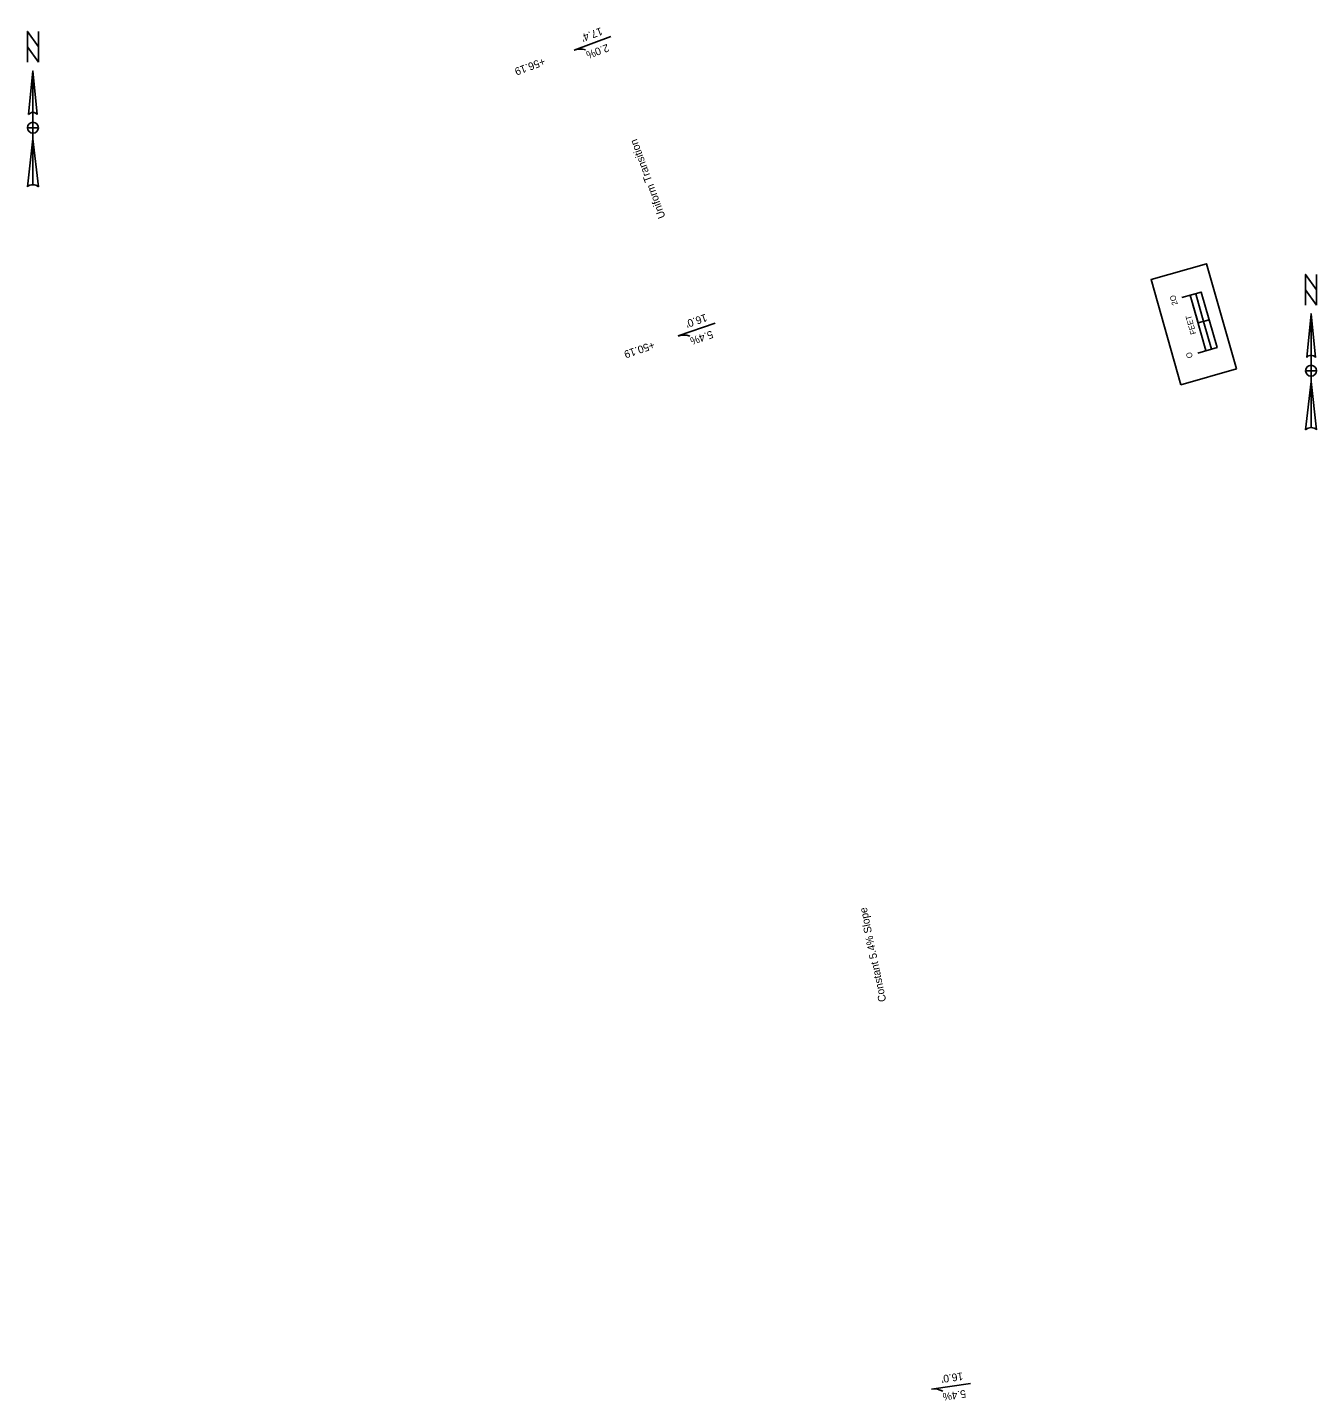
# Model space of a CAD drawing. Extents: x 20506035 to 20507470, y 7969245 to 7972296.
# Drawn here: x 20506246.2 to 20506694.1, y 7969471.6 to 7969948.7 of the extents above; entities that cross this region are included whole.
import ezdxf

# ---------------------------------------------------------------- set-up
doc = ezdxf.new("R2010")
doc.units = 0
doc.layers.add('_CIVIL_CONSTRUCTION', color=7, linetype='Continuous')
doc.layers.add('EdgeShoulder', color=7, linetype='Continuous')

msp = doc.modelspace()

# ---------------------------------------------------------------- linework, layer by layer
at = {"layer": '_CIVIL_CONSTRUCTION'}
for p, q in [((20506436.11, 7969940.82), (20506448.9, 7969945.57)), ((20506656.83, 7969847.13), (20506652.98, 7969846.04)), ((20506656.83, 7969847.13), (20506652.98, 7969846.04)), ((20506472.27, 7969841.51), (20506485.19, 7969845.94)), ((20506560.32, 7969475.54), (20506573.83, 7969477.47))]:
    msp.add_line(p, q, dxfattribs=at)
for points in [[(20506647.02, 7969824.59), (20506636.62, 7969861.14), (20506655.86, 7969866.61), (20506666.26, 7969830.06)], [(20506647.02, 7969824.59), (20506636.62, 7969861.14), (20506655.86, 7969866.61), (20506666.26, 7969830.06)], [(20506654.89, 7969846.58), (20506652.15, 7969856.2), (20506650.24, 7969855.66), (20506652.98, 7969846.04)], [(20506659.56, 7969837.51), (20506656.83, 7969847.13), (20506654.89, 7969846.58), (20506657.63, 7969836.96)]]:
    msp.add_lwpolyline(points, close=True, dxfattribs=at)
for points in [[(20506652.83, 7969835.6), (20506659.56, 7969837.51), (20506654.09, 7969856.75), (20506647.36, 7969854.84)], [(20506655.71, 7969836.42), (20506650.24, 7969855.66)]]:
    msp.add_lwpolyline(points, dxfattribs=at)
for centre, start, end in [((20506438.25, 7969935.04), 72.1798, 110.3304), ((20506474.27, 7969835.68), 70.7304, 108.881), ((20506561.19, 7969469.44), 59.952, 98.1027)]:
    msp.add_arc(centre, 6.16, start, end, dxfattribs=at)
at = {"layer": 'EdgeShoulder'}
for p, q in [((20506248.05, 7969933.64), (20506249.57, 7969918.43)), ((20506248.05, 7969933.64), (20506248.05, 7969894.09)), ((20506246.53, 7969918.43), (20506246.53, 7969918.43)), ((20506246.59, 7969918.57), (20506246.87, 7969918.89)), ((20506246.15, 7969893.33), (20506248.05, 7969910.06)), ((20506248.05, 7969911.96), (20506248.05, 7969911.96)), ((20506692.23, 7969849.22), (20506693.75, 7969834.01)), ((20506692.23, 7969849.22), (20506692.23, 7969809.67)), ((20506690.71, 7969834.01), (20506690.71, 7969834.01)), ((20506690.77, 7969834.15), (20506691.05, 7969834.46)), ((20506692.23, 7969827.54), (20506692.23, 7969827.54)), ((20506690.33, 7969808.9), (20506692.23, 7969825.64))]:
    msp.add_line(p, q, dxfattribs=at)
for points in [[(20506249.95, 7969936.68), (20506246.15, 7969942.01), (20506246.15, 7969947.33), (20506249.95, 7969942.01)], [(20506694.13, 7969852.26), (20506690.33, 7969857.58), (20506690.33, 7969862.91), (20506694.13, 7969857.58)]]:
    msp.add_lwpolyline(points, close=True, dxfattribs=at)
for points in [[(20506246.15, 7969936.68), (20506246.15, 7969947.33), (20506249.95, 7969942.01), (20506249.95, 7969947.33)], [(20506246.53, 7969918.43), (20506248.05, 7969933.64), (20506248.05, 7969919.19)], [(20506248.05, 7969911.96), (20506248.05, 7969913.87), (20506246.15, 7969913.87)], [(20506249.95, 7969913.87), (20506248.05, 7969913.87), (20506248.05, 7969915.77)], [(20506248.05, 7969894.09), (20506248.05, 7969910.06), (20506249.95, 7969893.33)], [(20506690.33, 7969852.26), (20506690.33, 7969862.91), (20506694.13, 7969857.58), (20506694.13, 7969862.91)], [(20506690.71, 7969834.01), (20506692.23, 7969849.22), (20506692.23, 7969834.77)], [(20506692.23, 7969827.54), (20506692.23, 7969829.44), (20506690.33, 7969829.44)], [(20506694.13, 7969829.44), (20506692.23, 7969829.44), (20506692.23, 7969831.34)], [(20506692.23, 7969809.67), (20506692.23, 7969825.64), (20506694.13, 7969808.91)]]:
    msp.add_lwpolyline(points, dxfattribs=at)
for centre, radius, start, end in [((20506248.05, 7969917.29), 1.9, 90.0204, 143.1257), ((20506248.05, 7969917.29), 1.9, 36.8481, 90.0218), ((20506248.05, 7969913.87), 1.9, 90, 180), ((20506248.05, 7969913.87), 1.9, 180, 270), ((20506248.05, 7969913.87), 1.9, 0, 90), ((20506248.05, 7969913.87), 1.9, 270, 360), ((20506248.05, 7969891.33), 2.76, 89.9894, 133.619), ((20506248.05, 7969891.33), 2.76, 46.4021, 90.0006), ((20506692.23, 7969832.86), 1.9, 90.0204, 143.1257), ((20506692.23, 7969832.87), 1.9, 36.8481, 90.0218), ((20506692.23, 7969829.44), 1.9, 90, 180), ((20506692.23, 7969829.44), 1.9, 180, 270), ((20506692.23, 7969829.44), 1.9, 0, 90), ((20506692.23, 7969829.44), 1.9, 270, 360), ((20506692.23, 7969806.91), 2.76, 89.9894, 133.619), ((20506692.23, 7969806.91), 2.76, 46.4021, 90.0006)]:
    msp.add_arc(centre, radius, start, end, dxfattribs=at)

# ---------------------------------------------------------------- texts
at = {"layer": '_CIVIL_CONSTRUCTION'}
for s, height, rotation, p in [("17.4'", 2.664, 200.4593, (20506445.42, 7969948.82)), ('2.0%', 2.664, 200.4593, (20506447.65, 7969943.06)), ('+56.19', 2.664, 200.3566, (20506425.51, 7969938.31)), ('Uniform Transition', 2.664, 110.1419, (20506467.91, 7969882.87)), ('2O', 2, 105.8739, (20506645.95, 7969852.49)), ("16.0'", 2.664, 199.0099, (20506481.78, 7969849.27)), ('FEET', 2, 105.8739, (20506652.37, 7969842.34)), ('5.4%', 2.664, 199.0099, (20506483.87, 7969843.46)), ('+50.19', 2.664, 198.9072, (20506463.62, 7969839.76)), ('O', 2, 105.8739, (20506651.17, 7969834.11)), ('Constant 5.4% Slope', 2.664, 101.7569, (20506544.61, 7969610.39)), ("16.0'", 2.664, 188.2315, (20506571.11, 7969481.38)), ('5.4%', 2.664, 188.2315, (20506572.08, 7969475.28))]:
    msp.add_text(s, height=height, rotation=rotation, dxfattribs=at).set_placement(p)

doc.saveas('drawing.dxf')
